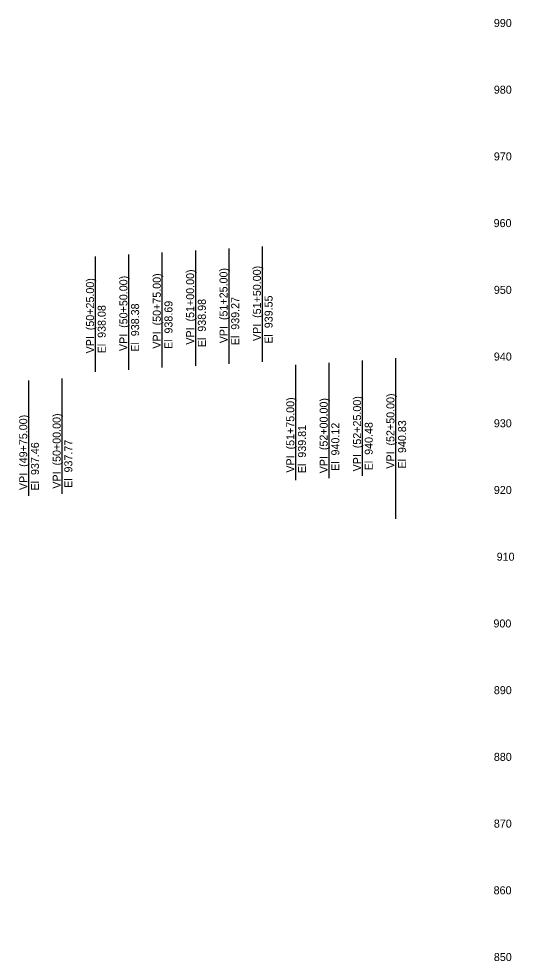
# Model space of a CAD drawing. Extents: x 16972094 to 16980746, y 12563782 to 12565536.
# Drawn here: x 16972094 to 16972465, y 12564288 to 12564994 of the extents above; entities that cross this region are included whole.
import ezdxf

# ---------------------------------------------------------------- set-up
doc = ezdxf.new("R2010")
doc.units = 0
for name, color, linetype in [('RD_EX_H2O_Ditch Bottom', 7, 'Continuous'), ('RD_EX_Misc', 7, 'Continuous'), ('RD_Sketch2', 7, 'Continuous')]:
    doc.layers.add(name, color=color, linetype=linetype)

msp = doc.modelspace()

# ---------------------------------------------------------------- linework, layer by layer
at = {"layer": 'RD_Sketch2'}
for p, q in [((16972276.47, 12564737.27), (16972276.47, 12564823.69)), ((16972151.47, 12564729.93), (16972151.47, 12564816.34)), ((16972176.47, 12564731.46), (16972176.47, 12564817.88)), ((16972201.47, 12564732.97), (16972201.47, 12564819.39)), ((16972226.47, 12564734.45), (16972226.47, 12564820.87)), ((16972251.47, 12564735.89), (16972251.47, 12564822.3)), ((16972376.47, 12564619.56), (16972376.47, 12564740.2)), ((16972301.47, 12564648.68), (16972301.47, 12564735.1)), ((16972326.47, 12564650.23), (16972326.47, 12564736.65)), ((16972351.47, 12564652.01), (16972351.47, 12564738.42)), ((16972126.47, 12564638.47), (16972126.47, 12564724.88)), ((16972101.47, 12564636.91), (16972101.47, 12564723.33))]:
    msp.add_line(p, q, dxfattribs=at)

# ---------------------------------------------------------------- texts
at = {"layer": 'RD_EX_H2O_Ditch Bottom'}
for s, p in [('VPI  (50+75.00)', (16972200.32, 12564747.22)), ('VPI  (51+00.00)', (16972225.32, 12564750.18)), ('VPI  (51+25.00)', (16972250.32, 12564751.26)), ('VPI  (51+50.00)', (16972275.32, 12564752.88)), ('VPI  (50+25.00)', (16972150.32, 12564743.64)), ('VPI  (50+50.00)', (16972175.32, 12564745.41)), ('El  938.69', (16972209.07, 12564746.95)), ('El  938.98', (16972234.07, 12564748.34)), ('El  939.27', (16972259.07, 12564749.81)), ('El  939.55', (16972284.07, 12564750.93)), ('El  938.08', (16972159.07, 12564743.7)), ('El  938.38', (16972184.07, 12564744.94)), ('VPI  (52+25.00)', (16972350.32, 12564655.21)), ('VPI  (52+50.00)', (16972375.32, 12564657.22)), ('VPI  (51+75.00)', (16972300.32, 12564654.3)), ('VPI  (52+00.00)', (16972325.32, 12564653.78)), ('VPI  (49+75.00)', (16972100.32, 12564641.23)), ('VPI  (50+00.00)', (16972125.32, 12564642.26)), ('El  939.81', (16972309.07, 12564653.92)), ('El  940.12', (16972334.07, 12564655.56)), ('El  940.48', (16972359.07, 12564656.03)), ('El  940.83', (16972384.07, 12564657.4)), ('El  937.46', (16972109.07, 12564640.91)), ('El  937.77', (16972134.07, 12564642.82))]:
    msp.add_text(s, height=6, rotation=90, dxfattribs=at).set_placement(p)
at = {"layer": 'RD_EX_Misc'}
for s, p in [('990', (16972449.8, 12564988.29)), ('980', (16972449.8, 12564938.29)), ('970', (16972449.8, 12564888.29)), ('960', (16972449.62, 12564838.29)), ('950', (16972449.8, 12564788.29)), ('940', (16972449.8, 12564738.29)), ('930', (16972449.8, 12564688.29)), ('920', (16972449.8, 12564638.29)), ('910', (16972451.92, 12564588.29)), ('900', (16972449.5, 12564538.29)), ('890', (16972449.8, 12564488.29)), ('880', (16972449.8, 12564438.29)), ('870', (16972449.8, 12564388.29)), ('860', (16972449.62, 12564338.29)), ('850', (16972449.8, 12564288.29))]:
    msp.add_text(s, height=6, dxfattribs=at).set_placement(p)

doc.saveas('drawing.dxf')
